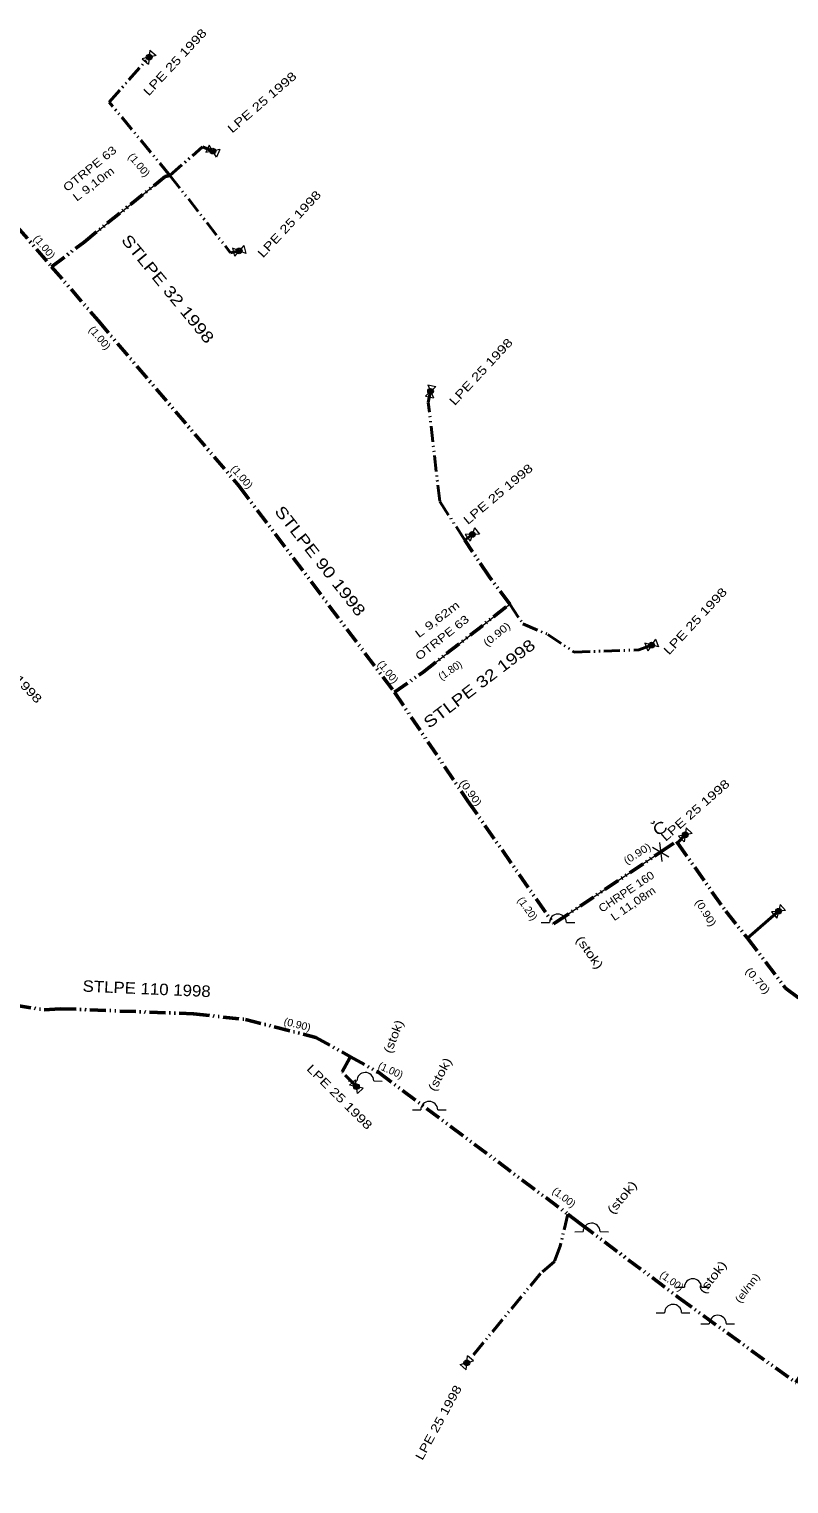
# Model space of a CAD drawing. Extents: x -648036 to -642998, y -1161549 to -1158141.
# Drawn here: x -644401.1 to -644334.7, y -1160279.6 to -1160152.4 of the extents above; entities that cross this region are included whole.
import ezdxf
from ezdxf.enums import TextEntityAlignment as Align

# ---------------------------------------------------------------- set-up
doc = ezdxf.new("R2010")
doc.units = 0
doc.header["$LTSCALE"] = 0.28
doc.linetypes.add('DASH_DOUBLE_DOT', pattern=[9.2, 5, -1.2, 0.3, -1.2, 0.3, -1.2])
for name, color, linetype, lineweight in [('12', 7, 'DASH_DOUBLE_DOT', 40), ('14', 7, 'Continuous', 13), ('15', 7, 'Continuous', 13), ('19', 7, 'Continuous', 13), ('8', 7, 'Continuous', 53)]:
    doc.layers.add(name, color=color, linetype=linetype, lineweight=lineweight)
for name, color, linetype in [('20', 7, 'Continuous'), ('22', 7, 'Continuous'), ('24', 7, 'Continuous'), ('27', 7, 'Continuous'), ('28', 7, 'Continuous')]:
    doc.layers.add(name, color=color, linetype=linetype)

msp = doc.modelspace()

# ---------------------------------------------------------------- linework, layer by layer
at = {"layer": '12'}
for p, q in [((-644363.01, -1160197.08), (-644362.34, -1160196.58)), ((-644343.72, -1160222.86), (-644344.39, -1160223.57))]:
    msp.add_line(p, q, dxfattribs=at)
at = {"layer": '12', "linetype": 'Continuous'}
msp.add_line((-644338.29, -1160231.89), (-644335.56, -1160229.54), dxfattribs=at)
at = {"layer": '12'}
for points in [[(-644388.78, -1160165.18), (-644394.09, -1160158.78), (-644392.37, -1160156.81), (-644390.6, -1160154.83)], [(-644388.78, -1160165.18), (-644385.93, -1160162.67), (-644385.03, -1160163.05)], [(-644388.78, -1160165.18), (-644383.48, -1160171.96), (-644382.73, -1160171.78)], [(-644363.01, -1160197.08), (-644365.19, -1160193.67), (-644366.19, -1160185.04), (-644365.99, -1160184.06)], [(-644359.07, -1160202.68), (-644357.92, -1160204.39), (-644355.74, -1160205.33), (-644353.44, -1160206.88), (-644347.77, -1160206.68), (-644346.66, -1160206.26)], [(-644372.48, -1160244.89), (-644373.72, -1160243.59), (-644372.99, -1160242.28)], [(-644353.99, -1160256.04), (-644354.66, -1160258.85), (-644355.16, -1160260.18), (-644356.37, -1160261.23), (-644362.82, -1160269.04)]]:
    msp.add_lwpolyline(points, dxfattribs=at)
at = {"layer": '14'}
for p, q in [((-644396.29, -1160171), (-644389.21, -1160165.28)), ((-644366.64, -1160208.62), (-644359.07, -1160202.68)), ((-644355.07, -1160230.54), (-644345.87, -1160224.36))]:
    msp.add_line(p, q, dxfattribs=at)
at = {"layer": '15'}
for p, q in [((-644389.999, -1160154.692), (-644391.201, -1160154.968)), ((-644390.53, -1160154.217), (-644390.67, -1160155.443)), ((-644390.53, -1160154.217), (-644389.999, -1160154.692)), ((-644391.201, -1160154.968), (-644390.67, -1160155.443)), ((-644385.355, -1160162.526), (-644385.633, -1160163.182)), ((-644384.427, -1160162.918), (-644385.633, -1160163.182)), ((-644384.704, -1160163.574), (-644385.355, -1160162.526)), ((-644384.427, -1160162.918), (-644384.704, -1160163.574)), ((-644382.323, -1160171.316), (-644383.137, -1160172.244)), ((-644382.323, -1160171.316), (-644382.157, -1160172.009)), ((-644383.302, -1160171.551), (-644383.137, -1160172.244)), ((-644382.157, -1160172.009), (-644383.302, -1160171.551)), ((-644365.54, -1160183.637), (-644366.439, -1160184.482)), ((-644366.238, -1160183.495), (-644365.742, -1160184.625)), ((-644366.238, -1160183.495), (-644365.54, -1160183.637)), ((-644366.439, -1160184.482), (-644365.742, -1160184.625)), ((-644361.723, -1160196.564), (-644362.956, -1160196.596)), ((-644362.956, -1160196.596), (-644362.531, -1160197.167)), ((-644362.149, -1160195.993), (-644362.531, -1160197.167)), ((-644362.149, -1160195.993), (-644361.723, -1160196.564)), ((-644347.256, -1160206.105), (-644347.005, -1160206.771)), ((-644346.063, -1160206.415), (-644347.256, -1160206.105)), ((-644346.315, -1160205.749), (-644347.005, -1160206.771)), ((-644346.315, -1160205.749), (-644346.063, -1160206.415)), ((-644346.717, -1160221.817), (-644346.501, -1160221.865)), ((-644346.444, -1160221.651), (-644346.501, -1160221.865)), ((-644343.633, -1160222.249), (-644343.807, -1160223.471)), ((-644343.633, -1160222.249), (-644343.115, -1160222.738)), ((-644343.115, -1160222.738), (-644344.324, -1160222.982)), ((-644344.324, -1160222.982), (-644343.807, -1160223.471)), ((-644346.598, -1160223.944), (-644345.142, -1160224.775)), ((-644345.98, -1160223.528), (-644345.759, -1160225.191)), ((-644334.946, -1160229.481), (-644336.173, -1160229.598)), ((-644336.173, -1160229.598), (-644335.71, -1160230.139)), ((-644335.41, -1160228.941), (-644335.71, -1160230.139)), ((-644335.41, -1160228.941), (-644334.946, -1160229.481)), ((-644356.325, -1160230.535), (-644355.59, -1160230.534)), ((-644354.104, -1160230.534), (-644353.37, -1160230.535)), ((-644373.175, -1160244.395), (-644372.44, -1160244.394)), ((-644372.57, -1160244.28), (-644373.085, -1160244.771)), ((-644371.875, -1160245.009), (-644373.085, -1160244.771)), ((-644372.39, -1160245.5), (-644372.57, -1160244.28)), ((-644371.875, -1160245.009), (-644372.39, -1160245.5)), ((-644370.954, -1160244.394), (-644370.22, -1160244.395)), ((-644367.585, -1160246.925), (-644366.85, -1160246.924)), ((-644365.364, -1160246.924), (-644364.63, -1160246.925)), ((-644353.385, -1160257.575), (-644352.65, -1160257.574)), ((-644351.164, -1160257.574), (-644350.43, -1160257.575)), ((-644344.525, -1160262.435), (-644343.79, -1160262.434)), ((-644342.304, -1160262.434), (-644341.57, -1160262.435)), ((-644346.265, -1160264.675), (-644345.53, -1160264.674)), ((-644344.044, -1160264.674), (-644343.31, -1160264.675)), ((-644342.355, -1160265.635), (-644341.62, -1160265.634)), ((-644340.134, -1160265.634), (-644339.4, -1160265.635)), ((-644363.415, -1160269.202), (-644362.225, -1160268.879)), ((-644362.866, -1160269.655), (-644363.415, -1160269.202)), ((-644362.866, -1160269.655), (-644362.774, -1160268.425)), ((-644362.225, -1160268.879), (-644362.774, -1160268.425))]:
    msp.add_line(p, q, dxfattribs=at)
for centre in [(-644354.8474, -1160230.5346), (-644371.6974, -1160244.3946), (-644366.1074, -1160246.9246), (-644351.9074, -1160257.5746), (-644343.0474, -1160262.4346), (-644344.7874, -1160264.6746), (-644340.8774, -1160265.6346)]:
    msp.add_arc(centre, 0.7431, 1.2748, 179.83951, dxfattribs=at)
at = {"layer": '19'}
for centre, radius in [((-644390.6, -1160154.83), 0.25), ((-644390.6, -1160154.83), 0.17), ((-644390.6, -1160154.83), 0.09), ((-644385.03, -1160163.05), 0.25), ((-644385.03, -1160163.05), 0.17), ((-644385.03, -1160163.05), 0.09), ((-644382.73, -1160171.78), 0.25), ((-644382.73, -1160171.78), 0.17), ((-644382.73, -1160171.78), 0.09), ((-644365.99, -1160184.06), 0.25), ((-644365.99, -1160184.06), 0.17), ((-644365.99, -1160184.06), 0.09), ((-644362.34, -1160196.58), 0.25), ((-644362.34, -1160196.58), 0.17), ((-644362.34, -1160196.58), 0.09), ((-644346.66, -1160206.26), 0.25), ((-644346.66, -1160206.26), 0.17), ((-644346.66, -1160206.26), 0.09), ((-644343.72, -1160222.86), 0.25), ((-644343.72, -1160222.86), 0.17), ((-644343.72, -1160222.86), 0.09), ((-644335.56, -1160229.54), 0.25), ((-644335.56, -1160229.54), 0.17), ((-644335.56, -1160229.54), 0.09), ((-644372.48, -1160244.89), 0.25), ((-644372.48, -1160244.89), 0.17), ((-644372.48, -1160244.89), 0.09), ((-644362.82, -1160269.04), 0.25), ((-644362.82, -1160269.04), 0.17), ((-644362.82, -1160269.04), 0.09)]:
    msp.add_circle(centre, radius, dxfattribs=at)
at = {"layer": '8', "linetype": 'DASH_DOUBLE_DOT'}
for points in [[(-644416.74, -1160162.85), (-644416.6, -1160163.5), (-644411.96, -1160164.76), (-644403.86, -1160167.66), (-644399.13, -1160173.16)], [(-644399.13, -1160173.16), (-644396.29, -1160171), (-644389.21, -1160165.28), (-644388.78, -1160165.18)], [(-644399.13, -1160173.16), (-644395.07, -1160177.88), (-644382.72, -1160192.37), (-644369.15, -1160210.39)], [(-644359.07, -1160202.68), (-644360.86, -1160200.27), (-644363.01, -1160197.08)], [(-644369.15, -1160210.39), (-644366.64, -1160208.62), (-644359.07, -1160202.68)], [(-644369.15, -1160210.39), (-644362.73, -1160219.91), (-644355.23, -1160230.65), (-644355.07, -1160230.54), (-644345.87, -1160224.36)], [(-644345.87, -1160224.36), (-644344.49, -1160223.43), (-644344.39, -1160223.57)], [(-644344.39, -1160223.57), (-644340.17, -1160229.55), (-644338.29, -1160231.89)], [(-644338.29, -1160231.89), (-644334.94, -1160236.28), (-644330.79, -1160239.46), (-644324.67, -1160243.3), (-644323.15, -1160244.26), (-644312.85, -1160251.24)], [(-644419.21, -1160232.69), (-644413.52, -1160234.74), (-644410.08, -1160236.59), (-644399.79, -1160238.16), (-644398.39, -1160238.07), (-644386.73, -1160238.52), (-644382.19, -1160239.01), (-644376.02, -1160240.58), (-644372.99, -1160242.28)], [(-644372.99, -1160242.28), (-644370.53, -1160243.66), (-644353.99, -1160256.04)], [(-644353.99, -1160256.04), (-644352.87, -1160256.88), (-644344.28, -1160263.37), (-644334.06, -1160270.77), (-644331.94, -1160267.75), (-644324.78, -1160272.5), (-644320.81, -1160275.07), (-644319.55, -1160275.89), (-644313.77, -1160279.64)]]:
    msp.add_lwpolyline(points, dxfattribs=at)

# ---------------------------------------------------------------- texts
at = {"layer": '15', "width": 1.25}
msp.add_text('C', height=1, rotation=31.244, dxfattribs=at).set_placement((-644345.6683, -1160222.7081), align=Align.CENTER)
at = {"layer": '20'}
for s, rotation, width, p in [('STLPE 32 1998', 309.397, 1.25, (-644389.3543, -1160175.4162)), ('STLPE 90 1998', 308.251, 1.25, (-644376.0378, -1160199.2079)), ('STLPE 32 1998', 37.242, 1.25, (-644361.4296, -1160210.0312)), ('STLPE 110 1998', 357.526, 1.1, (-644390.8386, -1160236.8158))]:
    msp.add_text(s, height=1, rotation=rotation, dxfattribs=dict(at, width=width)).set_placement(p, align=Align.CENTER)
at = {"layer": '22'}
for rotation, width, p in [(46.983, 1.3, (-644388.0727, -1160155.5213)), (40.68, 1.3, (-644380.4909, -1160159.0622)), (46.983, 1.3, (-644378.0727, -1160169.6813)), (46.983, 1.3, (-644361.3127, -1160182.6013)), (40.107, 1.3, (-644359.8466, -1160193.3375)), (46.983, 1.3, (-644342.5727, -1160204.4213)), (313.408, 1.3, (-644403.0391, -1160208.6823)), (41.253, 1.3, (-644342.5973, -1160220.9887)), (315.127, 1.3, (-644374.2156, -1160246.0546)), (61.306, 1.25, (-644364.9709, -1160274.452))]:
    msp.add_text('LPE 25 1998', height=0.75, rotation=rotation, dxfattribs=dict(at, width=width)).set_placement(p, align=Align.CENTER)
at = {"layer": '24'}
for s, rotation, width, p in [('OTRPE 63', 38.961, 1.25, (-644395.5756, -1160164.8578)), ('L 9,10m', 37.242, 1.25, (-644395.2533, -1160166.2017)), ('L 9,62m', 37.242, 1.35, (-644365.1973, -1160204.2844)), ('OTRPE 63', 38.388, 1.25, (-644364.7693, -1160205.8821)), ('CHRPE 160', 33.805, 1.1, (-644348.6762, -1160228.1246)), ('L 11,08m', 34.377, 1.15, (-644348.0816, -1160229.1551))]:
    msp.add_text(s, height=0.7, rotation=rotation, dxfattribs=dict(at, width=width)).set_placement(p, align=Align.CENTER)
at = {"layer": '27'}
for s, rotation, width, p in [('(1.00)', 309.97, 1.05, (-644391.7224, -1160164.4617)), ('(1.00)', 309.97, 1.05, (-644400.0124, -1160171.6317)), ('(1.00)', 310.543, 1.05, (-644395.1574, -1160179.5947)), ('(1.00)', 311.116, 1.05, (-644382.7328, -1160191.7583)), ('(0.90)', 38.961, 1.2, (-644359.9969, -1160205.5607)), ('(0.90)', 305.387, 1.15, (-644362.7373, -1160219.3628)), ('(0.90)', 32.659, 1.15, (-644347.7529, -1160224.7736)), ('(0.90)', 301.949, 1.15, (-644342.1986, -1160229.843)), ('(0.70)', 311.116, 1.2, (-644337.6154, -1160235.8293)), ('(0.90)', 346.067, 1.05, (-644377.7233, -1160239.7541)), ('(el/nn)', 53.285, 1.2, (-644338.0301, -1160262.6948))]:
    msp.add_text(s, height=0.65, rotation=rotation, dxfattribs=dict(at, width=width)).set_placement(p, align=Align.CENTER)
for s, rotation, p in [('(1.00)', 308.824, (-644369.9607, -1160208.8037)), ('(1.80)', 34.377, (-644364.099, -1160208.7255)), ('(1.20)', 305.387, (-644357.7706, -1160229.4978)), ('(1.00)', 336.326, (-644369.612, -1160243.7501)), ('(1.00)', 323.148, (-644354.5089, -1160254.8258)), ('(1.00)', 324.294, (-644345.0857, -1160262.1492))]:
    msp.add_text(s, height=0.65, rotation=rotation, dxfattribs=at).set_placement(p, align=Align.CENTER)
at = {"layer": '28'}
for rotation, width, p in [(305.387, 1.3, (-644352.3836, -1160233.3613)), (68.755, 1.2, (-644368.8855, -1160240.6424)), (61.306, 1.25, (-644364.8539, -1160243.997)), (50.42, 1.35, (-644348.9627, -1160254.8109)), (52.139, 1.3, (-644341.0439, -1160261.7787))]:
    msp.add_text('(stok)', height=0.75, rotation=rotation, dxfattribs=dict(at, width=width)).set_placement(p, align=Align.CENTER)

doc.saveas('drawing.dxf')
